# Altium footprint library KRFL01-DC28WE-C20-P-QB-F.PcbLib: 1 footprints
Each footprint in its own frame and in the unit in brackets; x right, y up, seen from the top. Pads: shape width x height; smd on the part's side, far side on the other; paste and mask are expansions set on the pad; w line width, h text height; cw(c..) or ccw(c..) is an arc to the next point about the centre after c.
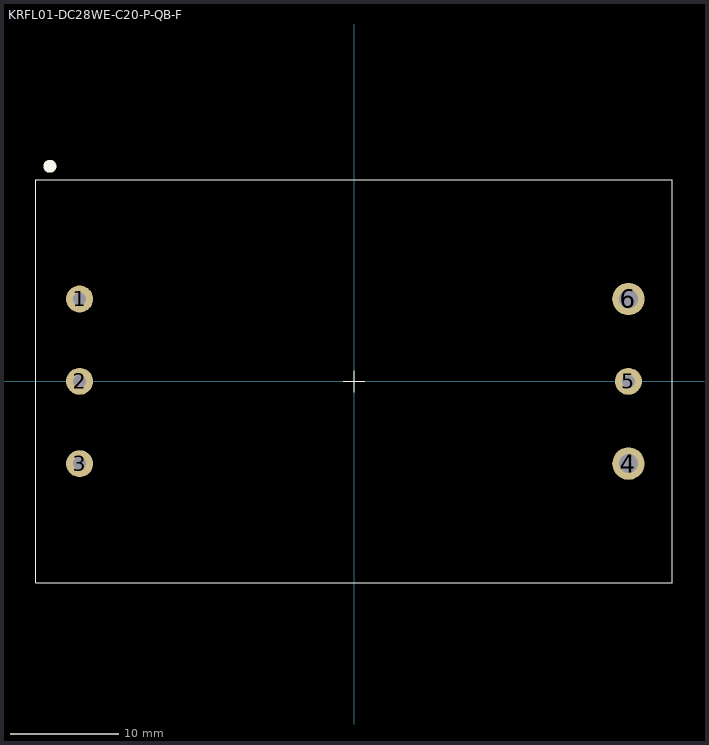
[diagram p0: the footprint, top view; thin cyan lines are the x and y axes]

## KRFL01-DC28WE-C20-P-QB-F [mm] "KRFL01-DC28WE-C20-P-QB-F"
height 12.7
pads (6):
  round 2.5 hole 1.2: 1(-25.4,7.62) 2(-25.4,0) 3(-25.4,-7.62) 5(25.4,0)
  round 3 hole 1.75: 4(25.4,-7.62) 6(25.4,7.62)
Top Overlay:
  circle w1: c-28.15,19.905 r0.1
  lines w0.1: -1,0 0,0 ; 0,-1 0,0 ; 0,1 0,0 ; 1,0 0,0 ; -29.45,-18.65 29.45,-18.65 29.45,18.65 -29.45,18.65 -29.45,-18.65
Bottom Overlay:
  circle w1: c-28.15,16.895 r0.1
  text "-VOUT" at 28.1,-9.291 h0.7
  text "CM_OUT" at 28.158,-1.99 h0.7
  text "+VOUT" at 28.1,6.009 h0.7
  text "-VIN" at -28.8,-8.849 h0.7
  text "CM_IN" at -28.742,-1.574 h0.7
  text "+VIN" at -28.8,6.396 h0.7
3D body "KRFL01-F.STEP": height 12.71, standoff -4.69, extent -29.21,-28 29.21,28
